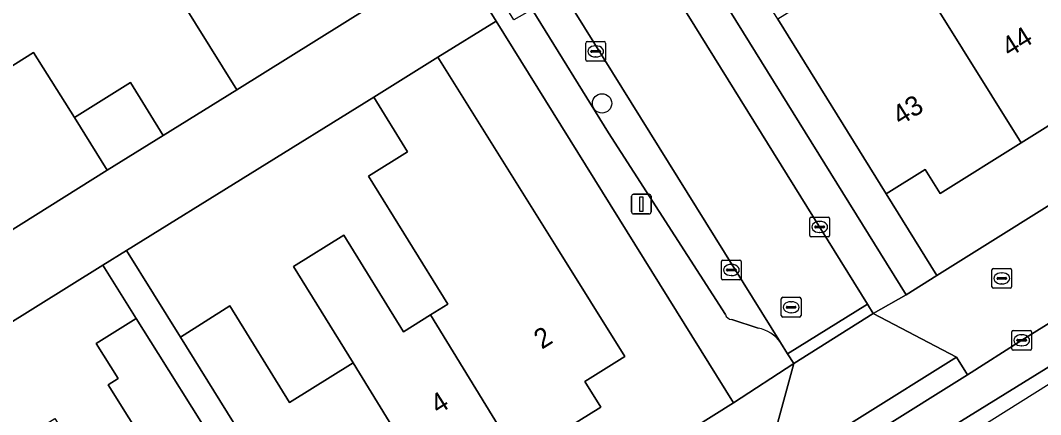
# Model space of a CAD drawing. Extents: x 159352 to 160617, y 385888 to 387323.
# Drawn here: x 159749.7 to 159801.4, y 385971.1 to 385991 of the extents above; entities that cross this region are included whole.
import ezdxf

# ---------------------------------------------------------------- set-up
doc = ezdxf.new("R2010")
doc.units = 0
for name, color, linetype in [('IMGEO_Boom', 7, 'Continuous'), ('IMGEO_Brandkraan', 7, 'Continuous'), ('IMGEO_Erf', 7, 'Continuous'), ('IMGEO_Fietspad_open', 7, 'Continuous'), ('IMGEO_Groenvoorziening', 7, 'Continuous'), ('IMGEO_Kolk', 7, 'Continuous'), ('IMGEO_Lichtmast', 7, 'Continuous'), ('IMGEO_Pand', 7, 'Continuous'), ('IMGEO_Pand_nummerreeks', 7, 'Continuous'), ('IMGEO_Parkeervlak_open', 7, 'Continuous'), ('IMGEO_Rijbaan_lokaal_open', 7, 'Continuous'), ('IMGEO_Rijbaan_regionaal_gesloten', 7, 'Continuous'), ('IMGEO_Rioolput', 7, 'Continuous'), ('IMGEO_Voetpad_open', 7, 'Continuous')]:
    doc.layers.add(name, color=color, linetype=linetype)

msp = doc.modelspace()

# ---------------------------------------------------------------- linework, layer by layer
at = {"layer": 'IMGEO_Boom'}
msp.add_circle((159779.199, 385986.838), 0.489, dxfattribs=at)
at = {"layer": 'IMGEO_Brandkraan'}
for p, q in [((159799.024, 385978.485), (159799.876, 385978.485)), ((159798.949, 385977.559), (159798.949, 385978.411)), ((159799.208, 385977.979), (159799.208, 385977.991)), ((159799.251, 385978.028), (159799.649, 385978.028)), ((159799.437, 385978.265), (159799.462, 385978.265)), ((159799.692, 385977.991), (159799.692, 385977.979)), ((159799.95, 385978.411), (159799.95, 385977.559)), ((159799.876, 385977.485), (159799.024, 385977.485)), ((159799.646, 385977.942), (159799.248, 385977.942)), ((159799.46, 385977.705), (159799.435, 385977.705))]:
    msp.add_line(p, q, dxfattribs=at)
for points in [[(159799.024, 385978.485), (159799.876, 385978.485)], [(159798.949, 385977.559), (159798.949, 385978.411)], [(159799.95, 385978.411), (159799.95, 385977.559)], [(159799.876, 385977.485), (159799.024, 385977.485)]]:
    msp.add_lwpolyline(points, dxfattribs=at)
for centre, radius, start, end in [((159799.026, 385978.409), 0.0765, 91.552, 178.448), ((159799.026, 385978.409), 0.0765, 91.552, 178.448), ((159799.874, 385978.409), 0.0765, 1.552, 88.448), ((159799.874, 385978.409), 0.0765, 1.552, 88.448), ((159799.248, 385977.988), 0.0403, 85.8775, 175.7526), ((159799.245, 385977.978), 0.0366, 178.938, 274.7102), ((159799.649, 385977.985), 0.043, 264.8664, 352.4533), ((159799.653, 385977.99), 0.0386, 1.7309, 96.639), ((159799.026, 385977.561), 0.0765, 181.552, 268.448), ((159799.026, 385977.561), 0.0765, 181.552, 268.448), ((159799.874, 385977.561), 0.0765, 271.552, 358.448), ((159799.874, 385977.561), 0.0765, 271.552, 358.448)]:
    msp.add_arc(centre, radius, start, end, dxfattribs=at)
for centre, major_axis, ratio, start_param, end_param in [((159799.436, 385977.985), (-0.387, 0.002), 0.722429, 4.712389, 7.853982), ((159799.461, 385977.985), (-0.39, 0.002), 0.717154, 1.570796, 4.712389)]:
    msp.add_ellipse(centre, major_axis=major_axis, ratio=ratio, start_param=start_param, end_param=end_param, dxfattribs=at)
at = {"layer": 'IMGEO_Erf'}
for points in [[(159743.864, 385985.314), (159750.4, 385989.412), (159752.465, 385986.118), (159755.303, 385987.897), (159756.968, 385985.218), (159760.702, 385987.531), (159757.239, 385993.08), (159754.026, 385998.227), (159753.441, 385997.869), (159753.321, 385998.062), (159750.006, 386003.387), (159746.677, 386008.735)], [(159803.052, 385986.476), (159800.428, 385984.839), (159796.328, 385982.28), (159795.571, 385983.493), (159793.585, 385982.265), (159796.167, 385978.135), (159829.32, 385998.863)], [(159746.736, 385966.308), (159749.764, 385968.215), (159749.038, 385969.373), (159751.478, 385970.903), (159754.533, 385966.031), (159757.235, 385967.726), (159754.181, 385972.598), (159754.683, 385972.913), (159753.567, 385974.69), (159755.595, 385975.963), (159753.911, 385978.646), (159724.622, 385960.426)]]:
    msp.add_lwpolyline(points, dxfattribs=at)
for points in [[(159773.833, 385991.005), (159770.888, 385989.171), (159776.867, 385979.596), (159780.345, 385974.026), (159778.323, 385972.772), (159779.132, 385971.473), (159775.166, 385969.005), (159774.974, 385968.886), (159774.466, 385969.701), (159770.553, 385967.259), (159766.642, 385964.818), (159766.359, 385965.265), (159764.599, 385964.157), (159767.196, 385960.007), (159785.861, 385971.689)], [(159766.112, 385980.174), (159769.142, 385975.287), (159770.515, 385976.138), (159771.385, 385976.678), (159767.365, 385983.163), (159769.345, 385984.391), (159767.632, 385987.153), (159755.113, 385979.394), (159757.842, 385975.011), (159760.341, 385976.596), (159763.371, 385971.709), (159766.592, 385973.706), (159763.562, 385978.593)]]:
    msp.add_lwpolyline(points, close=True, dxfattribs=at)
at = {"layer": 'IMGEO_Fietspad_open'}
for points in [[(159732.868, 385930.223), (159789.753, 385966.056), (159807.266, 385976.872), (159846.766, 386001.708), (159890.661, 386028.937)], [(159861.026, 386012.714), (159852.337, 386007.274), (159848.877, 386005.124), (159847.204, 386004.039), (159842.911, 386001.399), (159840.679, 386000), (159826.846, 385991.331), (159826.23, 385990.945), (159814.656, 385983.733), (159805.827, 385978.178), (159803.584, 385976.806), (159800.461, 385974.853), (159797.711, 385973.111), (159788.825, 385967.561), (159787.886, 385966.974), (159786.644, 385966.207), (159786.554, 385966.152), (159784.029, 385964.604), (159777.24, 385960.333), (159775.972, 385959.527), (159769.2, 385955.252), (159767.426, 385954.133), (159743.553, 385939.2)]]:
    msp.add_lwpolyline(points, dxfattribs=at)
at = {"layer": 'IMGEO_Groenvoorziening'}
msp.add_lwpolyline([(159781.555, 385998.167), (159794.607, 385977.16), (159796.167, 385978.135), (159793.585, 385982.265), (159788.109, 385991.097), (159784.847, 385996.333), (159783.057, 385999.185)], close=True, dxfattribs=at)
at = {"layer": 'IMGEO_Kolk'}
for p, q in [((159778.377, 385989.04), (159778.377, 385989.892)), ((159778.452, 385989.966), (159779.304, 385989.966)), ((159779.378, 385989.892), (159779.378, 385989.04)), ((159778.636, 385989.46), (159778.636, 385989.472)), ((159779.074, 385989.423), (159778.676, 385989.423)), ((159778.679, 385989.509), (159779.077, 385989.509)), ((159778.865, 385989.746), (159778.89, 385989.746)), ((159779.12, 385989.472), (159779.12, 385989.46)), ((159779.304, 385988.966), (159778.452, 385988.966)), ((159778.888, 385989.186), (159778.863, 385989.186)), ((159789.8, 385981.086), (159790.652, 385981.086)), ((159789.725, 385980.16), (159789.725, 385981.012)), ((159789.984, 385980.58), (159789.984, 385980.592)), ((159790.027, 385980.629), (159790.425, 385980.629)), ((159790.213, 385980.866), (159790.238, 385980.866)), ((159790.468, 385980.592), (159790.468, 385980.58)), ((159790.726, 385981.012), (159790.726, 385980.16)), ((159790.652, 385980.086), (159789.8, 385980.086)), ((159790.422, 385980.543), (159790.024, 385980.543)), ((159790.236, 385980.306), (159790.211, 385980.306)), ((159785.25, 385977.984), (159785.25, 385978.836)), ((159785.325, 385978.91), (159786.177, 385978.91)), ((159785.738, 385978.69), (159785.763, 385978.69)), ((159786.251, 385978.836), (159786.251, 385977.984)), ((159785.509, 385978.404), (159785.509, 385978.416)), ((159785.947, 385978.367), (159785.549, 385978.367)), ((159785.552, 385978.453), (159785.95, 385978.453)), ((159785.761, 385978.13), (159785.736, 385978.13)), ((159785.993, 385978.416), (159785.993, 385978.404)), ((159786.177, 385977.91), (159785.325, 385977.91)), ((159799.959, 385974.428), (159799.959, 385975.28)), ((159800.034, 385975.354), (159800.886, 385975.354)), ((159800.261, 385974.897), (159800.659, 385974.897)), ((159800.447, 385975.134), (159800.472, 385975.134)), ((159800.96, 385975.28), (159800.96, 385974.428)), ((159800.886, 385974.354), (159800.034, 385974.354)), ((159800.218, 385974.848), (159800.218, 385974.86)), ((159800.656, 385974.811), (159800.258, 385974.811)), ((159800.47, 385974.574), (159800.445, 385974.574)), ((159800.702, 385974.86), (159800.702, 385974.848))]:
    msp.add_line(p, q, dxfattribs=at)
for points in [[(159778.377, 385989.04), (159778.377, 385989.892)], [(159778.452, 385989.966), (159779.304, 385989.966)], [(159779.378, 385989.892), (159779.378, 385989.04)], [(159779.304, 385988.966), (159778.452, 385988.966)], [(159789.8, 385981.086), (159790.652, 385981.086)], [(159789.725, 385980.16), (159789.725, 385981.012)], [(159790.726, 385981.012), (159790.726, 385980.16)], [(159790.652, 385980.086), (159789.8, 385980.086)], [(159785.25, 385977.984), (159785.25, 385978.836)], [(159785.325, 385978.91), (159786.177, 385978.91)], [(159786.251, 385978.836), (159786.251, 385977.984)], [(159786.177, 385977.91), (159785.325, 385977.91)], [(159799.959, 385974.428), (159799.959, 385975.28)], [(159800.034, 385975.354), (159800.886, 385975.354)], [(159800.96, 385975.28), (159800.96, 385974.428)], [(159800.886, 385974.354), (159800.034, 385974.354)]]:
    msp.add_lwpolyline(points, dxfattribs=at)
for centre, radius, start, end in [((159778.454, 385989.89), 0.0765, 91.552, 178.448), ((159778.454, 385989.89), 0.0765, 91.552, 178.448), ((159779.302, 385989.89), 0.0765, 1.552, 88.448), ((159779.302, 385989.89), 0.0765, 1.552, 88.448), ((159778.676, 385989.469), 0.0403, 85.8775, 175.7526), ((159778.673, 385989.459), 0.0366, 178.938, 274.7102), ((159779.077, 385989.466), 0.043, 264.8664, 352.4533), ((159779.081, 385989.471), 0.0386, 1.7309, 96.639), ((159778.454, 385989.042), 0.0765, 181.552, 268.448), ((159778.454, 385989.042), 0.0765, 181.552, 268.448), ((159779.302, 385989.042), 0.0765, 271.552, 358.448), ((159779.302, 385989.042), 0.0765, 271.552, 358.448), ((159789.802, 385981.01), 0.0765, 91.552, 178.448), ((159789.802, 385981.01), 0.0765, 91.552, 178.448), ((159790.65, 385981.01), 0.0765, 1.552, 88.448), ((159790.65, 385981.01), 0.0765, 1.552, 88.448), ((159790.024, 385980.589), 0.0403, 85.8775, 175.7526), ((159790.021, 385980.579), 0.0366, 178.938, 274.7102), ((159790.425, 385980.586), 0.043, 264.8664, 352.4533), ((159790.429, 385980.591), 0.0386, 1.7309, 96.639), ((159789.802, 385980.162), 0.0765, 181.552, 268.448), ((159789.802, 385980.162), 0.0765, 181.552, 268.448), ((159790.65, 385980.162), 0.0765, 271.552, 358.448), ((159790.65, 385980.162), 0.0765, 271.552, 358.448), ((159785.327, 385978.834), 0.0765, 91.552, 178.448), ((159785.327, 385978.834), 0.0765, 91.552, 178.448), ((159786.175, 385978.834), 0.0765, 1.552, 88.448), ((159786.175, 385978.834), 0.0765, 1.552, 88.448), ((159785.327, 385977.986), 0.0765, 181.552, 268.448), ((159785.327, 385977.986), 0.0765, 181.552, 268.448), ((159785.549, 385978.413), 0.0403, 85.8775, 175.7526), ((159785.546, 385978.403), 0.0366, 178.938, 274.7102), ((159785.95, 385978.41), 0.043, 264.8664, 352.4533), ((159785.954, 385978.415), 0.0386, 1.7309, 96.639), ((159786.175, 385977.986), 0.0765, 271.552, 358.448), ((159786.175, 385977.986), 0.0765, 271.552, 358.448), ((159800.036, 385975.278), 0.0765, 91.552, 178.448), ((159800.036, 385975.278), 0.0765, 91.552, 178.448), ((159800.258, 385974.857), 0.0403, 85.8775, 175.7526), ((159800.663, 385974.859), 0.0386, 1.7309, 96.639), ((159800.884, 385975.278), 0.0765, 1.552, 88.448), ((159800.884, 385975.278), 0.0765, 1.552, 88.448), ((159800.036, 385974.43), 0.0765, 181.552, 268.448), ((159800.036, 385974.43), 0.0765, 181.552, 268.448), ((159800.255, 385974.847), 0.0366, 178.938, 274.7102), ((159800.659, 385974.854), 0.043, 264.8664, 352.4533), ((159800.884, 385974.43), 0.0765, 271.552, 358.448), ((159800.884, 385974.43), 0.0765, 271.552, 358.448)]:
    msp.add_arc(centre, radius, start, end, dxfattribs=at)
for centre, major_axis, ratio, start_param, end_param in [((159778.864, 385989.466), (-0.387, 0.002), 0.722429, 4.712389, 7.853982), ((159778.889, 385989.466), (-0.39, 0.002), 0.717154, 1.570796, 4.712389), ((159790.212, 385980.586), (-0.387, 0.002), 0.722429, 4.712389, 7.853982), ((159790.237, 385980.586), (-0.39, 0.002), 0.717154, 1.570796, 4.712389), ((159785.737, 385978.41), (-0.387, 0.002), 0.722429, 4.712389, 7.853982), ((159785.762, 385978.41), (-0.39, 0.002), 0.717154, 1.570796, 4.712389), ((159800.446, 385974.854), (-0.387, 0.002), 0.722429, 4.712389, 7.853982), ((159800.471, 385974.854), (-0.39, 0.002), 0.717154, 1.570796, 4.712389)]:
    msp.add_ellipse(centre, major_axis=major_axis, ratio=ratio, start_param=start_param, end_param=end_param, dxfattribs=at)
at = {"layer": 'IMGEO_Lichtmast'}
for p, q in [((159780.695, 385981.344), (159780.695, 385982.144)), ((159780.695, 385982.144), (159780.695, 385981.344)), ((159780.795, 385982.244), (159781.585, 385982.244)), ((159781.585, 385982.244), (159780.795, 385982.244)), ((159781.685, 385982.144), (159781.685, 385981.344)), ((159781.685, 385981.344), (159781.685, 385982.144)), ((159781.585, 385981.244), (159780.795, 385981.244)), ((159780.795, 385981.244), (159781.585, 385981.244))]:
    msp.add_line(p, q, dxfattribs=at)
msp.add_lwpolyline([(159781.115, 385982.119), (159781.265, 385982.119), (159781.265, 385981.369), (159781.115, 385981.369), (159781.115, 385982.119)], dxfattribs=at)
for centre, start, end in [((159780.795, 385982.144), 90, 180), ((159780.795, 385982.144), 90, 180), ((159781.585, 385982.144), 0, 90), ((159781.585, 385982.144), 360, 90), ((159780.795, 385981.344), 180, 270), ((159780.795, 385981.344), 180, 270), ((159781.585, 385981.344), 270, 0), ((159781.585, 385981.344), 270, 0)]:
    msp.add_arc(centre, 0.1, start, end, dxfattribs=at)
at = {"layer": 'IMGEO_Pand'}
for points in [[(159798.162, 386000.14), (159795.916, 385998.731), (159797.637, 385995.987), (159794.649, 385994.113), (159795.977, 385991.982), (159800.428, 385984.839), (159803.052, 385986.476), (159803.3, 385987.688), (159805.188, 385988.864)], [(159757.239, 385993.08), (159760.702, 385987.531), (159768.762, 385992.557), (159765.311, 385998.105)], [(159795.977, 385991.982), (159794.649, 385994.113), (159791.648, 385992.231), (159791.159, 385993.01), (159788.109, 385991.097), (159793.585, 385982.265), (159795.571, 385983.493), (159796.328, 385982.28), (159800.428, 385984.839)], [(159774.974, 385968.886), (159775.166, 385969.005), (159779.132, 385971.473), (159778.323, 385972.772), (159780.345, 385974.026), (159776.867, 385979.596), (159770.888, 385989.171), (159767.632, 385987.153), (159769.345, 385984.391), (159767.365, 385983.163), (159771.385, 385976.678), (159770.515, 385976.138), (159774.466, 385969.701)], [(159756.968, 385985.218), (159755.303, 385987.897), (159752.465, 385986.118), (159754.135, 385983.452)], [(159774.466, 385969.701), (159770.515, 385976.138), (159769.142, 385975.287), (159766.112, 385980.174), (159763.562, 385978.593), (159766.592, 385973.706), (159770.553, 385967.259)], [(159763.371, 385971.709), (159760.341, 385976.596), (159757.842, 385975.011), (159764.599, 385964.157), (159766.359, 385965.265), (159766.642, 385964.818), (159770.553, 385967.259), (159766.592, 385973.706)], [(159756.712, 385974.184), (159755.595, 385975.963), (159753.567, 385974.69), (159754.683, 385972.913), (159754.181, 385972.598), (159757.235, 385967.726), (159754.533, 385966.031), (159759.099, 385958.985), (159762.146, 385960.898), (159761.358, 385962.164), (159763.443, 385963.462)]]:
    msp.add_lwpolyline(points, close=True, dxfattribs=at)
at = {"layer": 'IMGEO_Parkeervlak_open'}
for points in [[(159788.248, 385974.74), (159762.791, 386015.603), (159752.658, 386031.759), (159750.194, 386035.775)], [(159750.25, 386032.416), (159773.04, 385995.833), (159775.658, 385991.589), (159779.531, 385985.355), (159785.45, 385976.166)], [(159785.772, 385975.904), (159787.108, 385975.466)]]:
    msp.add_lwpolyline(points, dxfattribs=at)
msp.add_lwpolyline([(159752.465, 385986.118), (159750.4, 385989.412), (159743.864, 385985.314), (159747.578, 385979.361), (159754.135, 385983.452)], close=True, dxfattribs=at)
for centre, radius, start, end in [((159785.789, 385976.253), 0.35, 194.4627, 267.2692), ((159786.814, 385973.747), 1.744, 34.7169, 80.3017)]:
    msp.add_arc(centre, radius, start, end, dxfattribs=at)
at = {"layer": 'IMGEO_Rijbaan_lokaal_open'}
for points in [[(159762.791, 386015.603), (159788.248, 385974.74), (159788.6, 385974.171), (159792.653, 385976.684), (159779.143, 385998.41), (159766.946, 386018.026), (159766.892, 386018.124)], [(159767.632, 385987.153), (159770.888, 385989.171), (159773.833, 385991.005), (159771.719, 385994.399), (159768.762, 385992.557), (159760.702, 385987.531), (159756.968, 385985.218), (159754.135, 385983.452), (159747.578, 385979.361), (159746.3, 385978.566), (159739.263, 385974.184), (159725.011, 385965.31), (159722.539, 385963.769), (159724.622, 385960.426), (159753.911, 385978.646), (159755.113, 385979.394)]]:
    msp.add_lwpolyline(points, close=True, dxfattribs=at)
at = {"layer": 'IMGEO_Rijbaan_regionaal_gesloten'}
for points in [[(159680.589, 385901.515), (159678.374, 385900.403), (159677.09, 385899.832), (159676.054, 385899.376), (159674.34, 385898.621), (159673.604, 385898.41), (159672.377, 385898.152), (159671.133, 385898.005), (159669.88, 385897.969), (159668.841, 385898.033), (159672.265, 385892.74), (159701.42, 385910.447), (159730.336, 385928.01), (160003.316, 386098.383), (160029.667, 386114.83), (160338.731, 386306.963), (160519.651, 386421.283), (160554.007, 386449.857), (160584.37, 386476.501)], [(160004.347, 386101.103), (160002.357, 386099.871), (159999.724, 386098.31), (159991.642, 386093.359), (159989.333, 386091.543), (159985.375, 386088.326), (159946.201, 386063.73), (159920.298, 386047.584), (159890.661, 386028.937), (159846.766, 386001.708), (159807.266, 385976.872), (159789.753, 385966.056), (159732.868, 385930.223), (159726.624, 385926.948)]]:
    msp.add_lwpolyline(points, dxfattribs=at)
at = {"layer": 'IMGEO_Rioolput'}
for p, q in [((159788.279, 385976.101), (159788.279, 385976.953)), ((159788.354, 385977.027), (159789.206, 385977.027)), ((159789.28, 385976.953), (159789.28, 385976.101)), ((159788.538, 385976.521), (159788.538, 385976.533)), ((159788.976, 385976.484), (159788.578, 385976.484)), ((159788.581, 385976.57), (159788.979, 385976.57)), ((159788.767, 385976.807), (159788.792, 385976.807)), ((159789.022, 385976.533), (159789.022, 385976.521)), ((159789.206, 385976.027), (159788.354, 385976.027)), ((159788.79, 385976.247), (159788.765, 385976.247))]:
    msp.add_line(p, q, dxfattribs=at)
for points in [[(159788.279, 385976.101), (159788.279, 385976.953)], [(159788.354, 385977.027), (159789.206, 385977.027)], [(159789.28, 385976.953), (159789.28, 385976.101)], [(159789.206, 385976.027), (159788.354, 385976.027)]]:
    msp.add_lwpolyline(points, dxfattribs=at)
for centre, radius, start, end in [((159788.356, 385976.951), 0.0765, 91.552, 178.448), ((159788.356, 385976.951), 0.0765, 91.552, 178.448), ((159789.204, 385976.951), 0.0765, 1.552, 88.448), ((159789.204, 385976.951), 0.0765, 1.552, 88.448), ((159788.578, 385976.53), 0.0403, 85.8775, 175.7526), ((159788.575, 385976.52), 0.0366, 178.938, 274.7102), ((159788.979, 385976.527), 0.043, 264.8664, 352.4533), ((159788.983, 385976.532), 0.0386, 1.7309, 96.639), ((159788.356, 385976.103), 0.0765, 181.552, 268.448), ((159788.356, 385976.103), 0.0765, 181.552, 268.448), ((159789.204, 385976.103), 0.0765, 271.552, 358.448), ((159789.204, 385976.103), 0.0765, 271.552, 358.448)]:
    msp.add_arc(centre, radius, start, end, dxfattribs=at)
for centre, major_axis, ratio, start_param, end_param in [((159788.766, 385976.527), (-0.387, 0.002), 0.722429, 4.712389, 7.853982), ((159788.791, 385976.527), (-0.39, 0.002), 0.717154, 1.570796, 4.712389)]:
    msp.add_ellipse(centre, major_axis=major_axis, ratio=ratio, start_param=start_param, end_param=end_param, dxfattribs=at)
at = {"layer": 'IMGEO_Voetpad_open'}
for points in [[(159727.232, 386069.448), (159724.652, 386067.823), (159726.053, 386067.427), (159739.998, 386045.377), (159742.641, 386041.129), (159743.822, 386039.222), (159746.307, 386035.207), (159771.719, 385994.399), (159773.833, 385991.005), (159785.861, 385971.689), (159788.912, 385973.68), (159788.6, 385974.171), (159788.248, 385974.74)], [(159785.45, 385976.166), (159779.531, 385985.355), (159775.658, 385991.589), (159774.723, 385991.063), (159772.117, 385995.273), (159773.04, 385995.833), (159750.25, 386032.416)], [(159873.502, 386026.485), (159829.32, 385998.863), (159796.167, 385978.135), (159794.607, 385977.16), (159792.94, 385976.214), (159797.16, 385973.993), (159797.711, 385973.111), (159800.461, 385974.853), (159803.584, 385976.806), (159801.872, 385979.534), (159805.819, 385982.005), (159806.226, 385981.402), (159807.431, 385982.161), (159807.551, 385981.977), (159821.981, 385991.005)], [(159779.143, 385998.41), (159792.653, 385976.684), (159792.94, 385976.214), (159794.607, 385977.16), (159781.555, 385998.167), (159780.497, 385999.87), (159782.041, 386000.826), (159781.076, 386002.383), (159770.784, 386018.94), (159766.532, 386025.622)], [(159787.108, 385975.466), (159785.772, 385975.904)], [(159786.554, 385966.152), (159786.644, 385966.207), (159787.886, 385966.974), (159787.335, 385967.856), (159788.912, 385973.68), (159785.861, 385971.689), (159767.196, 385960.007), (159766.053, 385959.292), (159736.793, 385940.979), (159733.652, 385939.014), (159740.1, 385938.269), (159740.644, 385937.383), (159743.553, 385939.2)]]:
    msp.add_lwpolyline(points, dxfattribs=at)
for points in [[(159757.842, 385975.011), (159755.113, 385979.394), (159753.911, 385978.646), (159755.595, 385975.963), (159756.712, 385974.184), (159763.443, 385963.462), (159766.053, 385959.292), (159767.196, 385960.007), (159764.599, 385964.157)], [(159788.912, 385973.68), (159792.94, 385976.214), (159792.653, 385976.684), (159788.6, 385974.171)], [(159797.16, 385973.993), (159792.94, 385976.214), (159788.912, 385973.68), (159787.335, 385967.856)], [(159787.886, 385966.974), (159788.825, 385967.561), (159797.711, 385973.111), (159797.16, 385973.993), (159787.335, 385967.856)]]:
    msp.add_lwpolyline(points, close=True, dxfattribs=at)
for centre, radius, start, end in [((159785.789, 385976.253), 0.35, 194.4627, 267.2692), ((159786.814, 385973.747), 1.744, 34.7169, 80.3017)]:
    msp.add_arc(centre, radius, start, end, dxfattribs=at)

# ---------------------------------------------------------------- texts
at = {"layer": 'IMGEO_Pand_nummerreeks'}
for s, rotation, p in [('44', 32.0283, (159799.838, 385989.149)), ('43', 32.0283, (159794.312, 385985.693)), ('2', 32.0782, (159776.148, 385974.371)), ('4', 32.0782, (159770.901, 385971.082))]:
    msp.add_text(s, height=1, rotation=rotation, dxfattribs=at).set_placement(p)

doc.saveas('drawing.dxf')
